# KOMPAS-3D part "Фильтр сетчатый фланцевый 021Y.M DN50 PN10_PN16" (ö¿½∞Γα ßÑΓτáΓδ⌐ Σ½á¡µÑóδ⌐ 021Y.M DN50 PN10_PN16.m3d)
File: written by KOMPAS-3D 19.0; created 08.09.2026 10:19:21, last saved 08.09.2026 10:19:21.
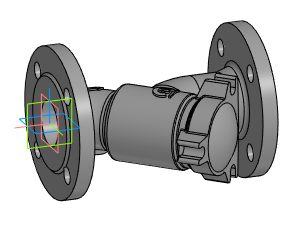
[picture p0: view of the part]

Document properties: Автор: Энергия; Полное имя файла: Z:\3.Личные\sachek\Dendor\_3D для проектировщиков\8.2 Фильтр сетчатый 021Y.M\021Y.M_STP\Фильтр сетчатый фланцевый 021Y.M DN50 PN10_PN16.m3d

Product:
- Part/product: Фильтр сетчатый фланцевый 021Y.M DN50 PN10_PN16

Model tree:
1. Операция без истории:1  (labels: Фильтр сетчатый фланцевый 021Y.M DN50 PN10_PN16)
